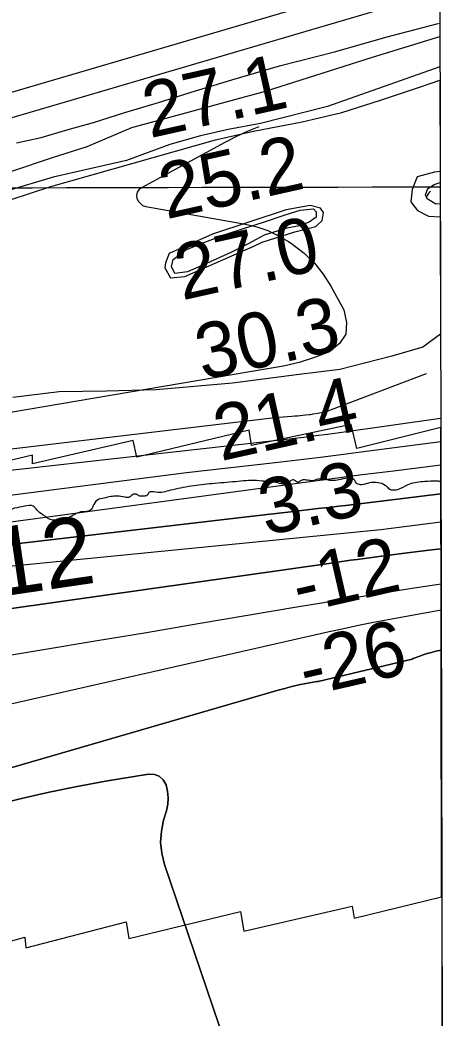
# Model space of a CAD drawing. Extents: x 3324104 to 3361979, y 612876 to 638273.
# Drawn here: x 3359286 to 3359808, y 623368 to 624575 of the extents above; entities that cross this region are included whole.
import ezdxf

# ---------------------------------------------------------------- set-up
doc = ezdxf.new("R2010")
doc.units = 0
for name, color, linetype in [('V-GRID-FRAM', 7, 'Continuous'), ('V-GRID-MAJR', 7, 'Continuous'), ('V-LEVE-TOET', 7, 'Continuous'), ('V-RIVR-EDGE', 7, 'Continuous'), ('V-RIVR-IDEN', 7, 'Continuous'), ('V-RIVR-RANG', 7, 'Continuous'), ('V-RRAP-RVMT', 7, 'Continuous'), ('V-SITE-VEGE', 7, 'Continuous'), ('V-SURV-LINE', 7, 'Continuous'), ('V-TOPO-DPTH', 7, 'Continuous'), ('V-TOPO-MAJR', 7, 'Continuous'), ('V-TOPO-MINR', 7, 'Continuous'), ('V-TOPO-WATR', 7, 'Continuous'), ('V-WETL-SWMP', 7, 'Continuous')]:
    doc.layers.add(name, color=color, linetype=linetype)

msp = doc.modelspace()

# ---------------------------------------------------------------- linework, layer by layer
at = {"layer": 'V-GRID-FRAM'}
msp.add_lwpolyline([(3328194.1, 636440.7), (3359767.9, 636495.9), (3359807.6, 618312.1), (3328217.9, 618256.9), (3328194.1, 636440.7)], dxfattribs=at)
at = {"layer": 'V-GRID-MAJR'}
msp.add_spline([(3328210, 624318.2), (3333474, 624325.5), (3338738.1, 624333.5), (3344002.2, 624342.3), (3349266.2, 624351.9), (3354530.3, 624362.2), (3359794.3, 624373.3)], degree=3, dxfattribs=at)
at = {"layer": 'V-LEVE-TOET'}
msp.add_lwpolyline([(3359281.4, 624426.6), (3359311.4, 624433), (3359344.2, 624442.8), (3359374.9, 624451.3), (3359412.5, 624463.2), (3359453.6, 624475.2), (3359498.3, 624489.3), (3359546.4, 624504.1), (3359600, 624519.6), (3359666.3, 624536.5), (3359730.4, 624554.8), (3359790.4, 624570.4), (3359793.9, 624571.3)], dxfattribs=at)
at = {"layer": 'V-RIVR-EDGE'}
msp.add_spline([(3359795.1, 624016.8), (3359789.3, 624017.3), (3359775.9, 624016.6), (3359757.2, 624013.5), (3359746.3, 624008.2), (3359732.2, 624007.9), (3359730.4, 624010), (3359728, 624012.1), (3359719.2, 624015.3), (3359708.9, 624015), (3359699.4, 624012.9), (3359694.1, 624014), (3359689.9, 624019.3), (3359671.6, 624018.6), (3359656.8, 624018.7), (3359645.9, 624019.4), (3359641.6, 624018), (3359635.7, 624018), (3359629, 624018.7), (3359625.4, 624017.7), (3359622.6, 624015.9), (3359617.7, 624018.4), (3359614.2, 624018.1), (3359610.6, 624015.6), (3359604.6, 624013.9), (3359595.5, 624015.6), (3359584.6, 624016.7), (3359572.2, 624017.8), (3359546.5, 624016.5), (3359518.3, 624014.1), (3359492.9, 624011), (3359467.9, 624006.1), (3359449.9, 624003.7), (3359441.8, 624003.3), (3359440, 624000.2), (3359435.1, 623999.1), (3359430.9, 623999.1), (3359426.3, 624001.3), (3359420.7, 623999.9), (3359418.5, 623997.8), (3359412.9, 623997.8), (3359403.4, 623999.2), (3359387.5, 623996.8), (3359379.4, 623994.3), (3359374.1, 623986.6), (3359371.6, 623982.4), (3359366.3, 623980.3), (3359359.3, 623979.9), (3359344.8, 623973.3), (3359335, 623971.5), (3359325.1, 623970.1), (3359313.8, 623976.2), (3359306.4, 623982.2), (3359301.9, 623987.1), (3359291.3, 623986.8), (3359279.3, 623984.4), (3359273.7, 623981.9), (3359267, 623977.3), (3359261.3, 623978.1), (3359255.7, 623977.4), (3359251.1, 623976.3), (3359243, 623974.2), (3359228.6, 623974.3), (3359217.3, 623972.5), (3359198.2, 623972.2), (3359192.2, 623965.9), (3359178.1, 623956.8), (3359170.7, 623951.5), (3359167.5, 623952.6), (3359164.7, 623955), (3359158.4, 623961.4), (3359155.9, 623961.8), (3359149.6, 623954.4), (3359141.5, 623949.5), (3359136.2, 623947.7), (3359123.5, 623947), (3359098.5, 623945), (3359077.3, 623942.9), (3359044.5, 623943), (3359031.8, 623941.6), (3359016, 623941), (3358974.8, 623938.2), (3358969.1, 623938.6), (3358965.2, 623941.8), (3358956.8, 623943.2), (3358951.2, 623942.5), (3358945.9, 623941.1), (3358933.2, 623943.3), (3358922.3, 623946.1), (3358918, 623945.1), (3358916.6, 623942.3), (3358911.7, 623940.2), (3358905.7, 623941.2), (3358905.3, 623943.7), (3358894.1, 623939.9), (3358884.5, 623934.9), (3358876.4, 623937.8), (3358872.9, 623938.5), (3358859.5, 623935), (3358851.1, 623937.1), (3358839.1, 623934), (3358822.9, 623932.6), (3358809.8, 623932.7), (3358783.7, 623926), (3358762.2, 623924), (3358742.8, 623920.5), (3358726.3, 623914.5), (3358716.4, 623909.3), (3358700.9, 623910.4), (3358684.3, 623909.7), (3358675.2, 623912.6), (3358672, 623914.7), (3358662.8, 623915.1), (3358657.9, 623914.7), (3358643.1, 623910.9), (3358638.9, 623912.6), (3358635.7, 623912.7), (3358618.8, 623909.2), (3358613.5, 623911.3), (3358612.8, 623913.8), (3358612.1, 623917.3), (3358598, 623912.7), (3358575.4, 623901.5), (3358539.1, 623886.8), (3358523.6, 623881.6), (3358513, 623878.4), (3358512.6, 623876), (3358502.4, 623874.9), (3358488.3, 623871.4), (3358468.9, 623862.3), (3358449.5, 623848.6), (3358433.3, 623838.8), (3358414.2, 623829.7), (3358401.2, 623829), (3358394.5, 623831.1), (3358393.4, 623834.3), (3358394.1, 623838.9), (3358393.4, 623842.1), (3358391.7, 623843.1), (3358389.2, 623843.1), (3358388.9, 623837.9), (3358385.3, 623837.9), (3358382.9, 623833.3), (3358381.1, 623829.1), (3358377.9, 623826.3), (3358373, 623828), (3358366.6, 623827.7), (3358362.4, 623823.8), (3358357.4, 623818.9), (3358350, 623817.5), (3358338.4, 623811.9), (3358324.6, 623804.9), (3358314.1, 623802.8), (3358302.1, 623799), (3358298.9, 623793.7), (3358291.8, 623793.3), (3358284.4, 623793), (3358276, 623792.3), (3358270, 623787.4), (3358261.9, 623780), (3358253.4, 623777.2), (3358241.4, 623775.1), (3358222.7, 623771), (3358210.7, 623766.4), (3358198.7, 623761.9), (3358192, 623752), (3358185.7, 623745.3), (3358171.6, 623742.9), (3358161.7, 623736.2), (3358141.9, 623726.4), (3358128.5, 623723.3), (3358116.5, 623720.8), (3358097.5, 623717), (3358087.3, 623715.6), (3358076.7, 623714.2), (3358064.4, 623711.8), (3358053.1, 623709), (3358034, 623701.7), (3358000.5, 623685.5), (3357981.1, 623681.4), (3357961.4, 623677.9), (3357943.4, 623676.2), (3357922.6, 623674.1), (3357909.2, 623666.7), (3357896.5, 623659), (3357880.3, 623648.1), (3357868.3, 623637.2), (3357853.4, 623620), (3357846.7, 623608.4), (3357833.3, 623593.3), (3357819.5, 623579.2)], degree=3, dxfattribs=at)
at = {"layer": 'V-RRAP-RVMT'}
for p, q in [((3359686.8, 624085.9), (3359565.9, 624060.3)), ((3359693.4, 624056.8), (3359686.8, 624085.9)), ((3359563, 624078.8), (3359427.4, 624046.3)), ((3359565.9, 624060.3), (3359563, 624078.8)), ((3359795, 624082), (3359693.4, 624056.8)), ((3359796.2, 623514.4), (3359795, 624082)), ((3359422.6, 624066.4), (3359301, 624038.1)), ((3359427.4, 624046.3), (3359422.6, 624066.4)), ((3359300.8, 624048.6), (3359170.3, 624017.4)), ((3359301, 624038.1), (3359300.8, 624048.6)), ((3359690.1, 623488.6), (3359796.2, 623514.4)), ((3359417.7, 623463.7), (3359552.8, 623496.4)), ((3359552.8, 623496.4), (3359556.6, 623472.9)), ((3359556.6, 623472.9), (3359687.8, 623503)), ((3359687.8, 623503), (3359690.1, 623488.6)), ((3359293, 623452.7), (3359414.2, 623484)), ((3359414.2, 623484), (3359417.7, 623463.7)), ((3359170.2, 623432.5), (3359291.6, 623465.3)), ((3359291.6, 623465.3), (3359293, 623452.7))]:
    msp.add_line(p, q, dxfattribs=at)
at = {"layer": 'V-SITE-VEGE'}
for p, q in [((3359771.9, 624494.5), (3359794.1, 624502.2)), ((3359794.1, 624502.2), (3359794.3, 624391.8)), ((3359722.3, 624478.2), (3359771.9, 624494.5)), ((3359675.5, 624463.4), (3359722.3, 624478.2)), ((3359627.3, 624452.1), (3359675.5, 624463.4)), ((3359568.6, 624440.7), (3359627.3, 624452.1)), ((3359522.4, 624430.1), (3359568.6, 624440.7)), ((3359323.3, 624373.6), (3359522.4, 624430.1)), ((3359787.6, 624391), (3359766.7, 624385.4)), ((3359794.3, 624391.8), (3359787.6, 624391)), ((3359766.7, 624385.4), (3359760.4, 624369.9)), ((3359273.7, 624357.4), (3359323.3, 624373.6)), ((3359760.4, 624369.9), (3359759, 624355.3)), ((3359637, 624350.8), (3359608.1, 624345.5)), ((3359649.4, 624347.6), (3359637, 624350.8)), ((3359759, 624355.3), (3359766.8, 624344.8)), ((3359608.1, 624345.5), (3359518.9, 624316)), ((3359653, 624342.1), (3359649.4, 624347.6)), ((3359651.4, 624332.4), (3359653, 624342.1)), ((3359766.8, 624344.8), (3359780.1, 624337.8)), ((3359643.8, 624325.2), (3359651.4, 624332.4)), ((3359780.1, 624337.8), (3359794.4, 624337.1)), ((3359794.4, 624337.1), (3359794.7, 624194.9)), ((3359518.9, 624316), (3359466.5, 624292.7)), ((3359579, 624306.2), (3359618.6, 624318.7)), ((3359618.6, 624318.7), (3359643.8, 624325.2)), ((3359569, 624301.4), (3359579, 624306.2)), ((3359466.5, 624292.7), (3359461.8, 624281.4)), ((3359485.4, 624264.7), (3359569, 624301.4)), ((3359461.8, 624281.4), (3359461, 624275.4)), ((3359461, 624275.4), (3359467.8, 624263)), ((3359467.8, 624263), (3359485.4, 624264.7)), ((3359794.7, 624194.9), (3359773.5, 624179.1)), ((3359773.5, 624179.1), (3359735.8, 624168.5)), ((3359735.8, 624168.5), (3359672.9, 624152.2)), ((3359620.5, 624145.7), (3359542.9, 624135.7)), ((3359672.9, 624152.2), (3359620.5, 624145.7)), ((3359542.9, 624135.7), (3359450.6, 624127.8)), ((3359333.1, 624125.4), (3359277.1, 624118.2)), ((3359390.4, 624126.2), (3359333.1, 624125.4)), ((3359450.6, 624127.8), (3359390.4, 624126.2))]:
    msp.add_line(p, q, dxfattribs=at)
at = {"layer": 'V-SURV-LINE'}
for points in [[(3358993.6, 624405.1), (3359793.8, 624640.4)], [(3359793.8, 624609.2), (3359002.1, 624376.4)]]:
    msp.add_lwpolyline(points, dxfattribs=at)
at = {"layer": 'V-TOPO-DPTH'}
msp.add_line((3359795.6, 623812.8), (3359795.5, 623861.1), dxfattribs=at)
for points in [[(3359795.1, 624002), (3359795, 624064.7), (3359704.9, 624052.9), (3359677.3, 624049.3), (3359649.7, 624045.9), (3359622.1, 624042.6), (3359594.5, 624039.3), (3359487.4, 624027.1), (3359163.3, 623985.8), (3358894, 623947.9), (3358857.7, 623942.3), (3358821.4, 623936.1), (3358785.3, 623928.8), (3358749.3, 623920.9), (3358664.1, 623901), (3358585.8, 623881.8), (3358507.8, 623861.6), (3358430.3, 623839.8)], [(3358412.2, 623776.3), (3358517.4, 623805.4), (3358622.8, 623833.5), (3358812.6, 623882.5), (3358823.5, 623885.2), (3358834.4, 623887.6), (3358845.3, 623889.8), (3358856.3, 623891.8), (3359563.8, 623974.6), (3359588.7, 623977.3), (3359613.5, 623980.1), (3359646.5, 623983.9), (3359654.9, 623984.9), (3359663.3, 623985.9), (3359671.6, 623986.9), (3359680, 623987.9), (3359795.1, 624002)], [(3358412.2, 623776.3), (3358517.4, 623805.4), (3358622.8, 623833.5), (3358812.6, 623882.5), (3358823.5, 623885.2), (3358834.4, 623887.6), (3358845.3, 623889.8), (3358856.3, 623891.8), (3359563.8, 623974.6), (3359588.7, 623977.3), (3359613.5, 623980.1), (3359646.5, 623983.9), (3359654.9, 623984.9), (3359663.3, 623985.9), (3359671.6, 623986.9), (3359680, 623987.9), (3359795.1, 624002)], [(3359795.1, 624002), (3359795.3, 623935.2), (3359780.5, 623933.5), (3359754.9, 623930.4), (3359729.3, 623927.1), (3359693.8, 623922.4), (3359686, 623921.4), (3359678.1, 623920.3), (3359670.2, 623919.2), (3359662.4, 623918.1), (3359158.6, 623846.6), (3359098.2, 623838.1), (3359037.8, 623829.6), (3358977.4, 623821.1), (3358891.8, 623809.2), (3358874.2, 623806.6), (3358856.6, 623803.8), (3358839.1, 623800.6), (3358821.6, 623797.2), (3358450, 623721.8)], [(3358450, 623721.8), (3358821.6, 623797.2), (3358839.1, 623800.6), (3358856.6, 623803.8), (3358874.2, 623806.6), (3358891.8, 623809.2), (3358977.4, 623821.1), (3359037.8, 623829.6), (3359098.2, 623838.1), (3359158.6, 623846.6), (3359662.4, 623918.1), (3359670.2, 623919.2), (3359678.1, 623920.3), (3359686, 623921.4), (3359693.8, 623922.4), (3359729.3, 623927.1), (3359754.9, 623930.4), (3359780.5, 623933.5), (3359795.3, 623935.2), (3359795.5, 623861.1)], [(3359795.5, 623861.1), (3359731.4, 623849.4), (3359713.5, 623846), (3359695.7, 623842.4), (3359677.9, 623838.7), (3359660.1, 623834.8), (3359194.2, 623729.2), (3359144, 623717.5), (3359093.9, 623705.5), (3359043.9, 623692.9), (3358994, 623680), (3358913.5, 623658.7), (3358903.9, 623656.1), (3358894.4, 623653.7), (3358884.8, 623651.2), (3358875.3, 623648.8), (3358126, 623516.1)], [(3359795.5, 623861.1), (3359731.4, 623849.4), (3359713.5, 623846), (3359695.7, 623842.4), (3359677.9, 623838.7), (3359660.1, 623834.8), (3359194.2, 623729.2), (3359144, 623717.5), (3359093.9, 623705.5), (3359043.9, 623692.9), (3358994, 623680), (3358913.5, 623658.7), (3358903.9, 623656.1), (3358894.4, 623653.7), (3358884.8, 623651.2), (3358875.3, 623648.8), (3358126, 623516.1)], [(3358928.6, 623570.1), (3359598.2, 623764.2), (3359606.5, 623766.5), (3359614.8, 623768.7), (3359623.2, 623770.6), (3359631.7, 623772.3), (3359645, 623774.9), (3359646.6, 623774.8), (3359760.5, 623801.9), (3359761.8, 623802.6), (3359768.7, 623805.2), (3359773.7, 623807), (3359778.7, 623808.6), (3359783.8, 623810), (3359789, 623811.3), (3359795.6, 623812.8)], [(3358928.6, 623570.1), (3359598.2, 623764.2), (3359606.5, 623766.5), (3359614.8, 623768.7), (3359623.2, 623770.6), (3359631.7, 623772.3), (3359645, 623774.9), (3359646.6, 623774.8), (3359760.5, 623801.9), (3359761.8, 623802.6), (3359768.7, 623805.2), (3359773.7, 623807), (3359778.7, 623808.6), (3359783.8, 623810), (3359789, 623811.3), (3359795.6, 623812.8), (3359798, 622708.4)], [(3359643, 623016.5), (3359460.5, 623553.5), (3359457.3, 623566.9), (3359455.8, 623580.3), (3359456.9, 623593.7), (3359459.6, 623607.2), (3359463, 623618.5), (3359464.6, 623626.4), (3359465.3, 623634.2), (3359464.4, 623642), (3359462.7, 623649.8), (3359459, 623655.8), (3359454.4, 623660.2), (3359448.4, 623662.2), (3359441.4, 623662.7), (3359389.2, 623654), (3359355.1, 623647.8), (3359321.1, 623641), (3359287.4, 623633.2), (3359253.8, 623624.8)], [(3359253.8, 623624.8), (3359287.4, 623633.2), (3359321.1, 623641), (3359355.1, 623647.8), (3359389.2, 623654), (3359441.4, 623662.7), (3359448.4, 623662.2), (3359454.4, 623660.2), (3359459, 623655.8), (3359462.7, 623649.8), (3359464.4, 623642), (3359465.3, 623634.2), (3359464.6, 623626.4), (3359463, 623618.5), (3359459.6, 623607.2), (3359456.9, 623593.7), (3359455.8, 623580.3), (3359457.3, 623566.9), (3359460.5, 623553.5), (3359643, 623016.5)]]:
    msp.add_lwpolyline(points, dxfattribs=at)
at = {"layer": 'V-TOPO-MAJR'}
msp.add_lwpolyline([(3359574.9, 624445.9), (3359574.7, 624445.8), (3359560.8, 624440.1), (3359547.2, 624433.7), (3359533.8, 624426.8), (3359432.7, 624372.2), (3359429.8, 624369.7), (3359427.8, 624366.8), (3359427, 624363.4), (3359427.2, 624359.6), (3359428.8, 624355.9), (3359434.2, 624350.9), (3359438, 624349.5), (3359558.6, 624328.2), (3359572.4, 624324.8), (3359585.9, 624320.3), (3359598.6, 624314.2), (3359611, 624307), (3359616.2, 624303.5), (3359629.8, 624292.9), (3359642.2, 624281.1), (3359652.8, 624267.6), (3359662.1, 624253.1), (3359677.8, 624224.3), (3359681.2, 624209), (3359680.2, 624195.2), (3359672.6, 624183.7), (3359660.5, 624173.7), (3359642.2, 624166.6), (3359623.6, 624160.6), (3359604.6, 624156.2), (3359585.2, 624153), (3358855.9, 624029.1)], dxfattribs=at)
at = {"layer": 'V-TOPO-MINR'}
for points in [[(3359777.4, 624146.9), (3359662.6, 624103.4), (3359658.6, 624102), (3359654.6, 624100.8), (3359650.5, 624099.8), (3359646.3, 624099), (3359640.2, 624098.1), (3359639.1, 624097.9), (3359636.9, 624097.6), (3359635.7, 624097.5), (3359631.4, 624097), (3359628.2, 624096.6), (3359624.9, 624096.3), (3359621.6, 624096), (3359618.3, 624095.7), (3359614.7, 624095.3), (3359609.6, 624094.9), (3359604.5, 624094.5), (3359599.5, 624094.1), (3359594.4, 624093.6), (3358840.4, 624004.2)], [(3359794.9, 624093.1), (3359672.5, 624075.8), (3359658.2, 624073.8), (3359643.8, 624071.9), (3359629.5, 624070.1), (3359615.1, 624068.4), (3358824.9, 623979.8), (3358817.8, 623978.4), (3358810.7, 623976.9), (3358803.6, 623975.2), (3358796.6, 623973.4), (3358699.8, 623947.1), (3358644.6, 623931.8), (3358589.5, 623915.9), (3358534.6, 623899.3), (3358479.8, 623882.2), (3357966.8, 623718.6), (3357954, 623714.4), (3357941.2, 623710.1), (3357928.5, 623705.8), (3357915.8, 623701.3), (3357248, 623461.7)], [(3359795, 624064.7), (3359704.9, 624052.9), (3359677.3, 624049.3), (3359649.7, 624045.9), (3359622.1, 624042.6), (3359594.5, 624039.3), (3359487.4, 624027.1), (3359163.3, 623985.8), (3358894, 623947.9), (3358857.7, 623942.3), (3358821.4, 623936.1), (3358785.3, 623928.8), (3358749.3, 623920.9), (3358664.1, 623901), (3358585.8, 623881.8), (3358507.8, 623861.6), (3358430.3, 623839.8)], [(3359795.1, 624036.4), (3359737.8, 624029.3), (3359696.7, 624024.3), (3358870, 623913.1), (3358849.8, 623909.4), (3358829.6, 623905.4), (3358809.6, 623900.8), (3358789.6, 623895.9), (3358137.7, 623726.6), (3358106.6, 623718.2), (3358075.7, 623709.6), (3358044.8, 623700.4), (3358014.1, 623690.9), (3357983.5, 623681), (3357953, 623670.8), (3357922.6, 623660.3), (3357892.3, 623649.4), (3357881.3, 623645.4), (3357845.6, 623632.3), (3357809.9, 623618.9), (3357774.4, 623605.4), (3357738.9, 623591.6), (3357198, 623379.8)], [(3359795.2, 623967.6), (3359722.4, 623958.3), (3358941.5, 623881.2), (3358929.4, 623880.2), (3358917.4, 623879.2), (3358905.3, 623878.2), (3358893.2, 623877.1), (3358884.1, 623876.3), (3358876.6, 623875.6), (3358869.1, 623874.7), (3358861.5, 623873.6), (3358854, 623872.5), (3358842.6, 623870.5), (3358839.1, 623869.9), (3358837.4, 623869.5), (3358835.6, 623869.1), (3358804.1, 623861), (3358786.7, 623856.4), (3358769.3, 623851.6), (3358752, 623846.7), (3358734.7, 623841.5), (3357991.5, 623614.9)], [(3359795.3, 623935.2), (3359780.5, 623933.5), (3359754.9, 623930.4), (3359729.3, 623927.1), (3359693.8, 623922.4), (3359686, 623921.4), (3359678.1, 623920.3), (3359670.2, 623919.2), (3359662.4, 623918.1), (3359158.6, 623846.6), (3359098.2, 623838.1), (3359037.8, 623829.6), (3358977.4, 623821.1), (3358891.8, 623809.2), (3358874.2, 623806.6), (3358856.6, 623803.8), (3358839.1, 623800.6), (3358821.6, 623797.2), (3358450, 623721.8)], [(3359795.4, 623892.6), (3359757.8, 623886.8), (3359723, 623881.4), (3359688.1, 623875.8), (3359653.3, 623870.1), (3359618.5, 623864.3), (3359563.5, 623854.9), (3359501.3, 623844.4), (3359439, 623833.8), (3359376.7, 623823.4), (3359314.4, 623813), (3358940.7, 623750.7), (3358906.8, 623745), (3358873, 623739.3), (3358839.1, 623733.5), (3358805.2, 623727.7), (3358764, 623720.7), (3358709.5, 623711.2), (3358655.1, 623701.4), (3358600.7, 623691.4), (3358546.4, 623681.1), (3358045.3, 623584.8)], [(3359795.5, 623861.1), (3359731.4, 623849.4), (3359713.5, 623846), (3359695.7, 623842.4), (3359677.9, 623838.7), (3359660.1, 623834.8), (3359194.2, 623729.2), (3359144, 623717.5), (3359093.9, 623705.5), (3359043.9, 623692.9), (3358994, 623680), (3358913.5, 623658.7), (3358903.9, 623656.1), (3358894.4, 623653.7), (3358884.8, 623651.2), (3358875.3, 623648.8), (3358126, 623516.1)], [(3359795.6, 623812.8), (3359789, 623811.3), (3359783.8, 623810), (3359778.7, 623808.6), (3359773.7, 623807), (3359768.7, 623805.2), (3359761.8, 623802.6), (3359760.5, 623801.9), (3359646.6, 623774.8), (3359645, 623774.9), (3359631.7, 623772.3), (3359623.2, 623770.6), (3359614.8, 623768.7), (3359606.5, 623766.5), (3359598.2, 623764.2), (3358928.6, 623570.1)], [(3359643, 623016.5), (3359460.5, 623553.5), (3359457.3, 623566.9), (3359455.8, 623580.3), (3359456.9, 623593.7), (3359459.6, 623607.2), (3359463, 623618.5), (3359464.6, 623626.4), (3359465.3, 623634.2), (3359464.4, 623642), (3359462.7, 623649.8), (3359459, 623655.8), (3359454.4, 623660.2), (3359448.4, 623662.2), (3359441.4, 623662.7), (3359389.2, 623654), (3359355.1, 623647.8), (3359321.1, 623641), (3359287.4, 623633.2), (3359253.8, 623624.8)]]:
    msp.add_lwpolyline(points, dxfattribs=at)
at = {"layer": 'V-TOPO-WATR'}
msp.add_lwpolyline([(3359795.1, 624002), (3359680, 623987.9), (3359671.6, 623986.9), (3359663.3, 623985.9), (3359654.9, 623984.9), (3359646.5, 623983.9), (3359613.5, 623980.1), (3359588.7, 623977.3), (3359563.8, 623974.6), (3358856.3, 623891.8), (3358845.3, 623889.8), (3358834.4, 623887.6), (3358823.5, 623885.2), (3358812.6, 623882.5), (3358622.8, 623833.5), (3358517.4, 623805.4), (3358412.2, 623776.3)], dxfattribs=at)
at = {"layer": 'V-WETL-SWMP'}
for p, q in [((3359712.4, 624530), (3359793.9, 624555.1)), ((3359793.9, 624555.1), (3359794, 624518.3)), ((3359583.1, 624489), (3359712.4, 624530)), ((3359794, 624518.3), (3359658, 624470.4)), ((3359421, 624445.2), (3359583.1, 624489)), ((3359658, 624470.4), (3359576.9, 624449.9)), ((3359576.9, 624449.9), (3359537.8, 624442.8)), ((3359367.2, 624422), (3359421, 624445.2)), ((3359504.2, 624435), (3359467.2, 624424.4)), ((3359537.8, 624442.8), (3359504.2, 624435)), ((3359467.2, 624424.4), (3359414.8, 624405.3)), ((3359325.3, 624408.6), (3359367.2, 624422)), ((3359275.7, 624392.4), (3359325.3, 624408.6)), ((3359414.8, 624405.3), (3359326, 624384.8)), ((3359326, 624384.8), (3359266.6, 624367.2)), ((3359779.3, 624371.4), (3359787, 624376.3)), ((3359787, 624376.3), (3359794.3, 624378.7)), ((3359794.3, 624378.7), (3359794.4, 624352.9)), ((3359776.5, 624363.7), (3359779.3, 624371.4)), ((3359778.6, 624358.8), (3359776.5, 624363.7)), ((3359789.1, 624352.5), (3359778.6, 624358.8)), ((3359794.4, 624352.9), (3359789.1, 624352.5))]:
    msp.add_line(p, q, dxfattribs=at)
msp.add_lwpolyline([(3359606.6, 624339.4), (3359624.8, 624345.1), (3359640.9, 624346.5), (3359644.4, 624343), (3359644.4, 624336.7), (3359636, 624330.4), (3359624.1, 624326.2), (3359608.8, 624323.4), (3359581.5, 624314.9), (3359562, 624304.3), (3359541, 624293.8), (3359511.7, 624280.4), (3359488.6, 624270.6), (3359473.2, 624268.4), (3359469, 624276.8), (3359471.1, 624285.2), (3359486.4, 624297.1), (3359509.5, 624306.3), (3359534, 624315.5), (3359557.7, 624323.2), (3359579.4, 624330.3)], close=True, dxfattribs=at)
msp.add_arc((3359809.2, 624345.2), 35.2, 139.3282, 153.4405, dxfattribs=at)

# ---------------------------------------------------------------- texts
at = {"layer": 'V-RIVR-IDEN'}
msp.add_text(' 2012', height=83, rotation=8.3852, dxfattribs=at).set_placement((3359105, 623854.2))
at = {"layer": 'V-RIVR-RANG'}
for s, rotation, p in [('27.1', 12.5983, (3359443, 624432)), ('25.2', 12.5983, (3359462.8, 624333.9)), ('27.0', 12.5983, (3359482, 624235.8)), ('30.3', 12.5983, (3359506.9, 624138.9)), ('21.4', 12.5983, (3359528.9, 624041.3)), ('3.3', 12.5983, (3359583.4, 623951)), ('-12', 12.8825, (3359623.5, 623857.2)), ('-26', 12.8825, (3359631.7, 623756.5))]:
    msp.add_text(s, height=67, rotation=rotation, dxfattribs=at).set_placement(p)

doc.saveas('drawing.dxf')
